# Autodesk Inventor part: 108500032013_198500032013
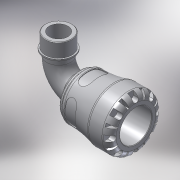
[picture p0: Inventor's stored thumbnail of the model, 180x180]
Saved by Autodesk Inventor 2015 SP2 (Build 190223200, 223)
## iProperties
Created: 2016-12
Part Number: 108500032013_198500032013
Material: PVC-Piping
Description: PLASSON 90° ELBOW WITH THREADED MALE OFFTAKE 32X1.1/4" SERIES 1
Document SubType Name: Modeling
Designer: KIM
Mass: 161.51 g
Surface Area: 349.026 cm^2
Volume: 115.365 cm^3
Density: 1.4 g/cm^3
Appearance: Smooth - White
Author: KIM
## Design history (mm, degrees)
derived "1085.ipt"
feature "Solid1::1085.ipt"
tag "TaggingFeature1"
body "Solid1"
other parameters: "d1" = 22.26, "d2" = 32, "d4" = 58, "d8" = 49.3, "d13" = 7.2, "d14" = 7.2, "d15" = 0, "d17" = 360 deg, "d19" = 8 deg, "d20" = 0.64, "d21" = 0.64, "d22" = 8 deg, "d24" = 0, "d26" = 360 deg, "d33" = 5.8, "d43" = 45.24, "d51" = 0.58, "d54" = 11.2, "d55" = 7.04, "d57" = 14.112, "d58" = 0, "d74" = 0, "d78" = 53, "d82" = 0.64, "d115" = 360 deg, "d207" = 90 deg, "d228" = 9.52, "d247" = 1.16, "d248" = 3.18, "d268" = 27.115, "d269" = 3.18, "d270" = 81, "d276" = 41.91, "d277" = 21, "d278" = 46.101, "d279" = 54, "d280" = 23.1, "d281" = 6.2865, "d283" = 37.719, "d286" = 0, "d287" = 0, "d288" = 29.337, "d290" = 3.7605, "d292" = 30 deg, "d_" = 32, "E_" = 58, "l_" = 53, "A_" = 81, "A_1" = 54, "l_2" = 21, "R_" = 41.91, "d9" = 9, "d11" = 58, "d289" = 29.337
